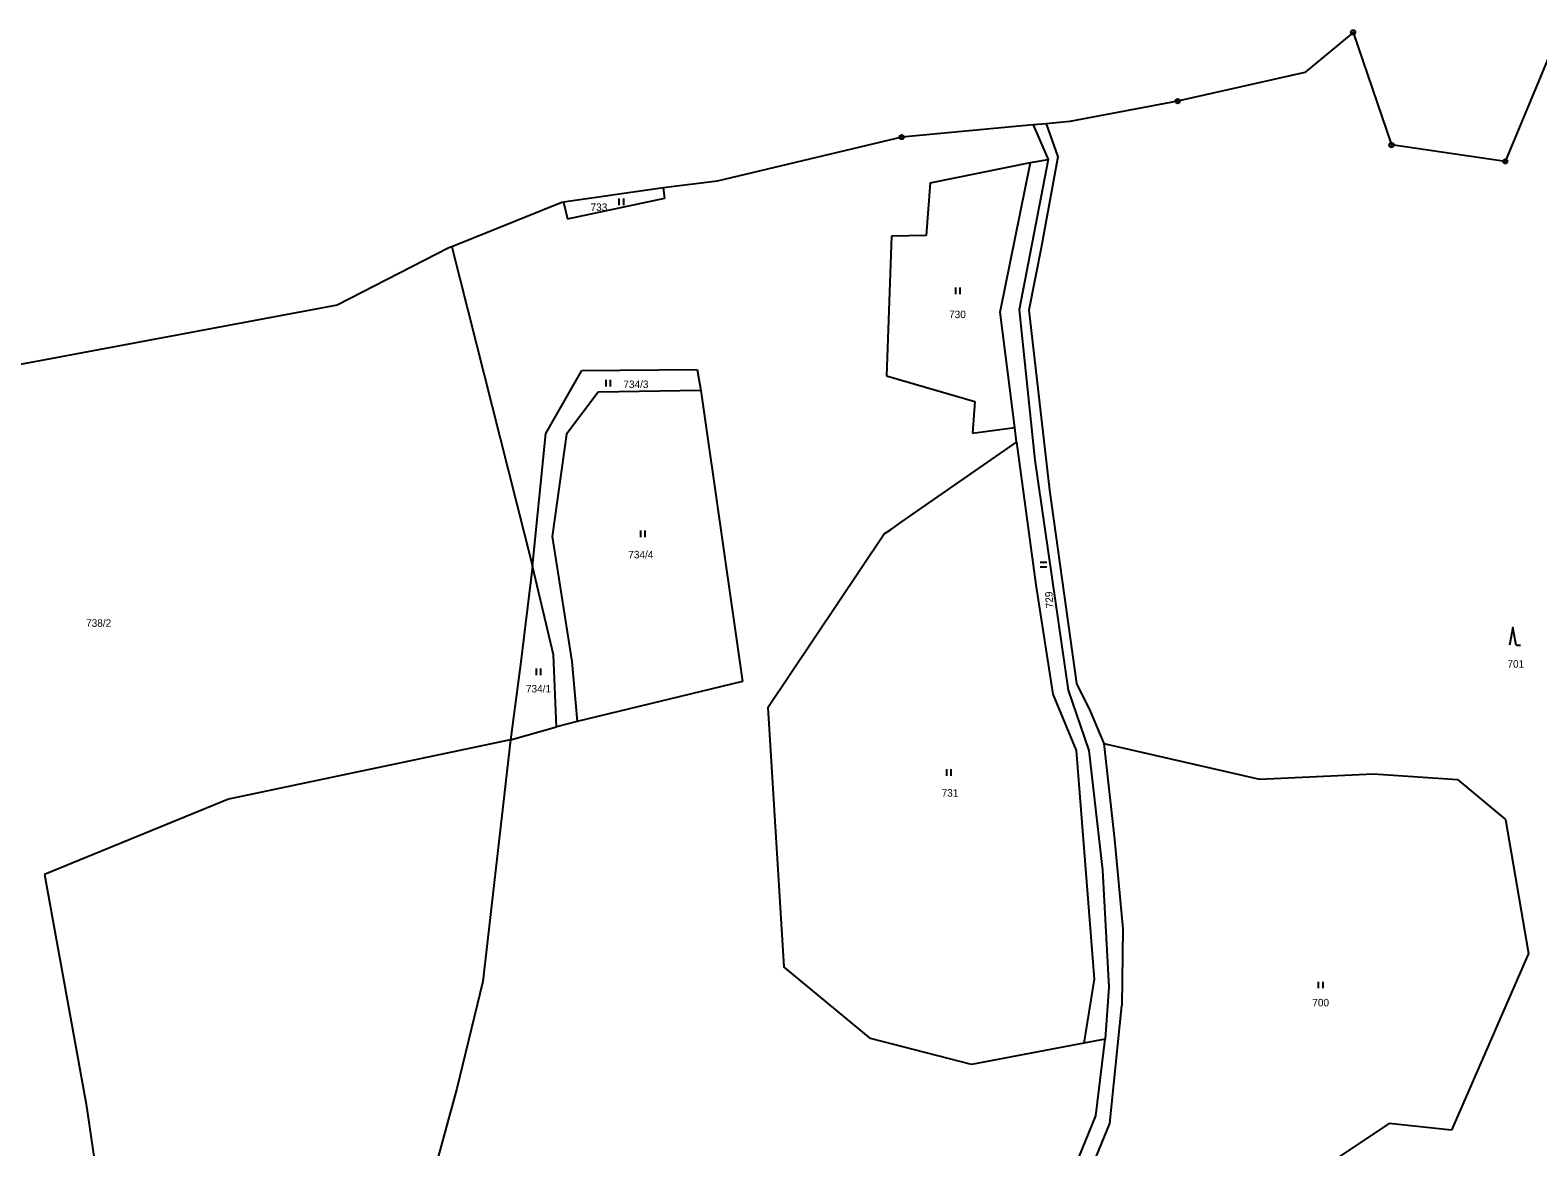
# Model space of a CAD drawing. Extents: x -744132 to -742433, y -984679 to -982287.
# Drawn here: x -743052.8 to -742711, y -982540.5 to -982287.3 of the extents above; entities that cross this region are included whole.
import ezdxf

# ---------------------------------------------------------------- set-up
doc = ezdxf.new("R2010")
doc.units = 0
doc.header["$LTSCALE"] = 0.68
for name, color, linetype, lineweight in [('1', 7, 'Continuous', 25), ('3', 7, 'Continuous', 25), ('8', 7, 'Continuous', 25)]:
    doc.layers.add(name, color=color, linetype=linetype, lineweight=lineweight)
doc.layers.add('2', color=7, linetype='Continuous')

msp = doc.modelspace()

# ---------------------------------------------------------------- linework, layer by layer
at = {"layer": '1'}
for p, q in [((-742752.9, -982287.8), (-742763.88, -982296.9)), ((-742752.9, -982287.8), (-742744.19, -982313.33)), ((-742708.43, -982293.09), (-742718.4, -982317.06)), ((-742763.88, -982296.9), (-742792.69, -982303.39)), ((-742792.69, -982303.39), (-742817.09, -982308.04)), ((-742822.47, -982308.5), (-742825.46, -982308.75)), ((-742817.09, -982308.04), (-742822.47, -982308.5)), ((-742822.47, -982308.5), (-742819.86, -982316.04)), ((-742855.22, -982311.55), (-742897.09, -982321.5)), ((-742825.46, -982308.75), (-742855.22, -982311.55)), ((-742825.46, -982308.75), (-742822.06, -982316.59)), ((-742718.4, -982317.06), (-742744.19, -982313.33)), ((-742832.94, -982351.2), (-742826.07, -982317.31)), ((-742822.06, -982316.59), (-742828.57, -982350.68)), ((-742819.86, -982316.04), (-742823.58, -982336.66)), ((-742897.09, -982321.5), (-742909.24, -982323.03)), ((-742848.81, -982321.9), (-742849.72, -982333.84)), ((-742909.78, -982323.1), (-742931.94, -982326.29)), ((-742930.97, -982330.11), (-742908.94, -982325.38)), ((-742909.24, -982323.03), (-742909.78, -982323.1)), ((-742908.94, -982325.38), (-742909.24, -982323.03)), ((-742932.26, -982326.34), (-742957.24, -982336.41)), ((-742931.94, -982326.29), (-742932.26, -982326.34)), ((-742931.94, -982326.29), (-742930.97, -982330.11)), ((-742857.55, -982333.98), (-742858.68, -982365.7)), ((-742849.72, -982333.84), (-742857.55, -982333.98)), ((-742957.87, -982336.66), (-742983.25, -982349.62)), ((-742957.24, -982336.41), (-742957.87, -982336.66)), ((-742957.24, -982336.41), (-742938.91, -982408.83)), ((-742823.58, -982336.66), (-742826.41, -982350.8)), ((-742983.25, -982349.62), (-743058.69, -982363.77)), ((-742829.61, -982377.39), (-742832.94, -982351.2)), ((-742828.57, -982350.68), (-742825.02, -982384.82)), ((-742826.41, -982350.8), (-742821.76, -982391.61)), ((-742935.92, -982378.77), (-742927.75, -982364.48)), ((-742927.75, -982364.48), (-742901.6, -982364.23)), ((-742901.6, -982364.23), (-742900.79, -982369.02)), ((-742858.68, -982365.7), (-742838.68, -982371.52)), ((-742924.03, -982369.36), (-742931.19, -982378.86)), ((-742900.79, -982369.02), (-742924.03, -982369.36)), ((-742900.79, -982369.02), (-742891.32, -982434.97)), ((-742838.68, -982371.52), (-742839.22, -982378.66)), ((-742938.91, -982408.83), (-742935.92, -982378.77)), ((-742931.19, -982378.86), (-742934.44, -982402.07)), ((-742839.22, -982378.66), (-742829.61, -982377.39)), ((-742829.18, -982380.74), (-742829.61, -982377.39)), ((-742855.34, -982398.82), (-742829.18, -982380.74)), ((-742829.18, -982380.74), (-742824.83, -982413.01)), ((-742825.02, -982384.82), (-742817.52, -982436.93)), ((-742821.76, -982391.61), (-742815.57, -982435.42)), ((-742859.18, -982401.5), (-742857.78, -982400.54)), ((-742857.78, -982400.54), (-742855.34, -982398.82)), ((-742934.44, -982402.07), (-742929.98, -982430.43)), ((-742885.62, -982440.86), (-742859.18, -982401.5)), ((-742938.91, -982408.83), (-742941.64, -982431.07)), ((-742934.16, -982428.95), (-742938.91, -982408.83)), ((-742824.83, -982413.01), (-742820.97, -982437.82)), ((-742941.64, -982431.07), (-742943.89, -982448.18)), ((-742933.49, -982445.23), (-742934.16, -982428.95)), ((-742929.98, -982430.43), (-742928.81, -982444.06)), ((-742891.32, -982434.97), (-742928.81, -982444.06)), ((-742820.97, -982437.82), (-742815.71, -982450.57)), ((-742817.52, -982436.93), (-742812.82, -982450.62)), ((-742815.57, -982435.42), (-742812.53, -982441.69)), ((-742885.62, -982440.86), (-742881.95, -982499.64)), ((-742812.53, -982441.69), (-742809.39, -982449.01)), ((-742943.89, -982448.18), (-742933.49, -982445.23)), ((-742928.81, -982444.06), (-742933.49, -982445.23)), ((-742943.89, -982448.18), (-743007.88, -982461.62)), ((-742943.89, -982448.18), (-742950.17, -982502.98)), ((-742815.71, -982450.57), (-742811.62, -982502.42)), ((-742812.82, -982450.62), (-742809.72, -982477.71)), ((-742809.39, -982449.01), (-742774.12, -982457.09)), ((-742809.39, -982449.01), (-742807.02, -982470.76)), ((-742774.12, -982457.09), (-742748.25, -982455.88)), ((-742748.25, -982455.88), (-742729.21, -982457.15)), ((-742729.21, -982457.15), (-742718.36, -982466.27)), ((-743007.88, -982461.62), (-743049.6, -982478.68)), ((-742718.36, -982466.27), (-742713.11, -982496.66)), ((-742807.02, -982470.76), (-742805.07, -982491.06)), ((-743049.6, -982478.68), (-743040.15, -982530.76)), ((-742809.72, -982477.71), (-742808.31, -982504.29)), ((-742805.07, -982491.06), (-742805.34, -982508.44)), ((-742862.28, -982515.93), (-742881.95, -982499.64)), ((-742713.11, -982496.66), (-742730.59, -982536.66)), ((-742950.17, -982502.98), (-742956.06, -982527.23)), ((-742811.62, -982502.42), (-742813.91, -982516.98)), ((-742808.31, -982504.29), (-742809.11, -982516.04)), ((-742808.03, -982535.17), (-742805.34, -982508.44)), ((-742839.44, -982521.77), (-742862.28, -982515.93)), ((-742813.91, -982516.98), (-742839.44, -982521.77)), ((-742809.11, -982516.04), (-742813.91, -982516.98)), ((-742811.21, -982533.39), (-742809.11, -982516.04)), ((-742956.06, -982527.23), (-742966.36, -982564.55)), ((-743040.15, -982530.76), (-743029.77, -982599.85)), ((-742820.87, -982557.06), (-742811.21, -982533.39)), ((-742816.77, -982556.28), (-742808.03, -982535.17)), ((-742744.69, -982535.17), (-742768.89, -982551.2)), ((-742730.59, -982536.66), (-742744.69, -982535.17))]:
    msp.add_line(p, q, dxfattribs=at)
msp.add_lwpolyline([(-742848.81, -982321.9), (-742826.07, -982317.31), (-742822.06, -982316.59)], dxfattribs=at)
at = {"layer": '3'}
for p, q in [((-742919.251, -982326.96), (-742919.251, -982325.46)), ((-742918.25, -982326.96), (-742918.25, -982325.46)), ((-742842.951, -982347.14), (-742842.951, -982345.64)), ((-742841.95, -982347.14), (-742841.95, -982345.64)), ((-742922.221, -982368.08), (-742922.221, -982366.58)), ((-742921.22, -982368.08), (-742921.22, -982366.58)), ((-742914.381, -982402.26), (-742914.381, -982400.76)), ((-742913.38, -982402.26), (-742913.38, -982400.76)), ((-742822.37, -982408.02), (-742823.87, -982408.02)), ((-742822.37, -982409.021), (-742823.87, -982409.021)), ((-742715.95, -982426.72), (-742714.954, -982426.72)), ((-742938.021, -982433.5), (-742938.021, -982432)), ((-742937.02, -982433.5), (-742937.02, -982432)), ((-742845.011, -982456.35), (-742845.011, -982454.85)), ((-742844.01, -982456.35), (-742844.01, -982454.85)), ((-742760.711, -982504.51), (-742760.711, -982503.01)), ((-742759.71, -982504.51), (-742759.71, -982503.01))]:
    msp.add_line(p, q, dxfattribs=at)
msp.add_lwpolyline([(-742715.95, -982426.72), (-742716.7, -982422.72), (-742717.45, -982426.72)], dxfattribs=at)
at = {"layer": '8'}
for centre, radius in [((-742752.9, -982287.7999), 0.5), ((-742752.9, -982287.7999), 0.0303), ((-742792.69, -982303.3899), 0.5), ((-742792.69, -982303.3899), 0.0303), ((-742855.22, -982311.5499), 0.5), ((-742855.22, -982311.5499), 0.0303), ((-742744.19, -982313.3299), 0.5), ((-742744.19, -982313.3299), 0.0303), ((-742718.4, -982317.0599), 0.5), ((-742718.4, -982317.0599), 0.0303)]:
    msp.add_circle(centre, radius, dxfattribs=at)

# ---------------------------------------------------------------- texts
at = {"layer": '2'}
for s, p in [('733', (-742925.77, -982328.285)), ('730', (-742844.49, -982352.585)), ('734/3', (-742918.33, -982368.435)), ('734/4', (-742917.22, -982407.045)), ('738/2', (-743040.13, -982422.555)), ('701', (-742717.91, -982431.825)), ('734/1', (-742940.42, -982437.445)), ('731', (-742846.18, -982461.075)), ('700', (-742762.15, -982508.615))]:
    msp.add_text(s, height=1.7, dxfattribs=at).set_placement(p)
msp.add_text('729', height=1.7, rotation=94, dxfattribs=at).set_placement((-742820.806, -982418.29))

doc.saveas('drawing.dxf')
